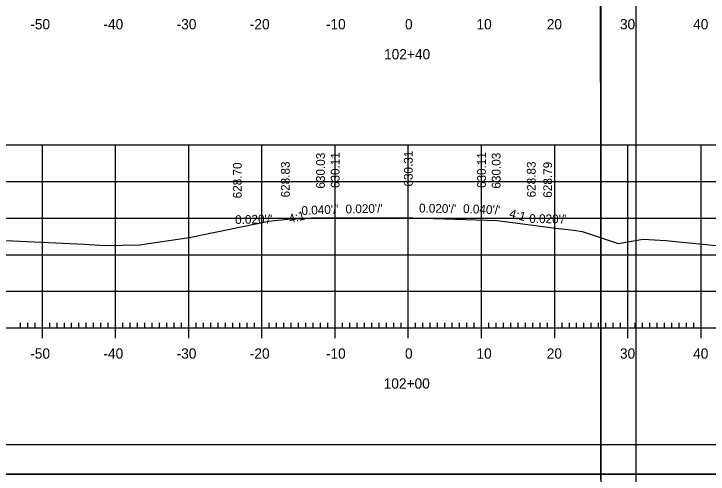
# Model space of a CAD drawing. Extents: x 1381471 to 1382703, y 370300 to 371487.
# Drawn here: x 1382082.7 to 1382177.6, y 370633.8 to 370696.7 of the extents above; entities that cross this region are included whole.
import ezdxf

# ---------------------------------------------------------------- set-up
doc = ezdxf.new("R2010")
doc.units = 0
for name, color, linetype in [('Level 26', 7, 'Continuous'), ('Level 45', 7, 'Continuous'), ('Level 6', 7, 'Continuous')]:
    doc.layers.add(name, color=color, linetype=linetype)

msp = doc.modelspace()

# ---------------------------------------------------------------- linework, layer by layer
at = {"layer": 'Level 26'}
for points in [[(1381834.365, 370760.966), (1382167.705, 370760.966), (1382167.705, 370547.628), (1381834.365, 370547.628)], [(1382080.692, 370757.071), (1382100.312, 370757.071), (1382100.312, 370747.191), (1382116.424, 370747.191), (1382139.624, 370747.191), (1382139.624, 370714.521), (1382162.831, 370714.521), (1382162.952, 370551.611), (1381846.772, 370551.611), (1381846.772, 370757.071)]]:
    msp.add_lwpolyline(points, close=True, dxfattribs=at)
at = {"layer": 'Level 45'}
for p, q in [((1381996.613, 370678.782), (1382276.613, 370678.782)), ((1382086.613, 370653.782), (1382086.613, 370678.782)), ((1382096.613, 370653.782), (1382096.613, 370678.782)), ((1382106.613, 370653.782), (1382106.613, 370678.782)), ((1382116.613, 370653.782), (1382116.613, 370678.782)), ((1382126.613, 370653.782), (1382126.613, 370678.782)), ((1382136.613, 370653.782), (1382136.613, 370678.782)), ((1382146.613, 370653.782), (1382146.613, 370678.782)), ((1382156.613, 370653.782), (1382156.613, 370678.782)), ((1382166.613, 370653.782), (1382166.613, 370678.782)), ((1382176.613, 370653.782), (1382176.613, 370678.782)), ((1381996.613, 370673.782), (1382276.613, 370673.782)), ((1381996.613, 370668.782), (1382276.613, 370668.782)), ((1381996.613, 370663.782), (1382276.613, 370663.782)), ((1381996.613, 370658.782), (1382276.613, 370658.782)), ((1382086.613, 370652.382), (1382086.613, 370655.182)), ((1382096.613, 370652.382), (1382096.613, 370655.182)), ((1382106.613, 370652.382), (1382106.613, 370655.182)), ((1382116.613, 370652.382), (1382116.613, 370655.182)), ((1382126.613, 370652.382), (1382126.613, 370655.182)), ((1382136.613, 370652.382), (1382136.613, 370655.182)), ((1382146.613, 370652.382), (1382146.613, 370655.182)), ((1382156.613, 370652.382), (1382156.613, 370655.182)), ((1382166.613, 370652.382), (1382166.613, 370655.182)), ((1382176.613, 370652.382), (1382176.613, 370655.182)), ((1381996.613, 370653.782), (1382276.613, 370653.782)), ((1381996.613, 370653.782), (1382276.613, 370653.782)), ((1382083.613, 370653.782), (1382083.613, 370654.482)), ((1382084.613, 370653.782), (1382084.613, 370654.482)), ((1382085.613, 370653.782), (1382085.613, 370654.482)), ((1382087.613, 370653.782), (1382087.613, 370654.482)), ((1382088.613, 370653.782), (1382088.613, 370654.482)), ((1382089.613, 370653.782), (1382089.613, 370654.482)), ((1382090.613, 370653.782), (1382090.613, 370654.482)), ((1382091.613, 370653.782), (1382091.613, 370654.482)), ((1382092.613, 370653.782), (1382092.613, 370654.482)), ((1382093.613, 370653.782), (1382093.613, 370654.482)), ((1382094.613, 370653.782), (1382094.613, 370654.482)), ((1382095.613, 370653.782), (1382095.613, 370654.482)), ((1382097.613, 370653.782), (1382097.613, 370654.482)), ((1382098.613, 370653.782), (1382098.613, 370654.482)), ((1382099.613, 370653.782), (1382099.613, 370654.482)), ((1382100.613, 370653.782), (1382100.613, 370654.482)), ((1382101.613, 370653.782), (1382101.613, 370654.482)), ((1382102.613, 370653.782), (1382102.613, 370654.482)), ((1382103.613, 370653.782), (1382103.613, 370654.482)), ((1382104.613, 370653.782), (1382104.613, 370654.482)), ((1382105.613, 370653.782), (1382105.613, 370654.482)), ((1382107.613, 370653.782), (1382107.613, 370654.482)), ((1382108.613, 370653.782), (1382108.613, 370654.482)), ((1382109.613, 370653.782), (1382109.613, 370654.482)), ((1382110.613, 370653.782), (1382110.613, 370654.482)), ((1382111.613, 370653.782), (1382111.613, 370654.482)), ((1382112.613, 370653.782), (1382112.613, 370654.482)), ((1382113.613, 370653.782), (1382113.613, 370654.482)), ((1382114.613, 370653.782), (1382114.613, 370654.482)), ((1382115.613, 370653.782), (1382115.613, 370654.482)), ((1382117.613, 370653.782), (1382117.613, 370654.482)), ((1382118.613, 370653.782), (1382118.613, 370654.482)), ((1382119.613, 370653.782), (1382119.613, 370654.482)), ((1382120.613, 370653.782), (1382120.613, 370654.482)), ((1382121.613, 370653.782), (1382121.613, 370654.482)), ((1382122.613, 370653.782), (1382122.613, 370654.482)), ((1382123.613, 370653.782), (1382123.613, 370654.482)), ((1382124.613, 370653.782), (1382124.613, 370654.482)), ((1382125.613, 370653.782), (1382125.613, 370654.482)), ((1382127.613, 370653.782), (1382127.613, 370654.482)), ((1382128.613, 370653.782), (1382128.613, 370654.482)), ((1382129.613, 370653.782), (1382129.613, 370654.482)), ((1382130.613, 370653.782), (1382130.613, 370654.482)), ((1382131.613, 370653.782), (1382131.613, 370654.482)), ((1382132.613, 370653.782), (1382132.613, 370654.482)), ((1382133.613, 370653.782), (1382133.613, 370654.482)), ((1382134.613, 370653.782), (1382134.613, 370654.482)), ((1382135.613, 370653.782), (1382135.613, 370654.482)), ((1382137.613, 370653.782), (1382137.613, 370654.482)), ((1382138.613, 370653.782), (1382138.613, 370654.482)), ((1382139.613, 370653.782), (1382139.613, 370654.482)), ((1382140.613, 370653.782), (1382140.613, 370654.482)), ((1382141.613, 370653.782), (1382141.613, 370654.482)), ((1382142.613, 370653.782), (1382142.613, 370654.482)), ((1382143.613, 370653.782), (1382143.613, 370654.482)), ((1382144.613, 370653.782), (1382144.613, 370654.482)), ((1382145.613, 370653.782), (1382145.613, 370654.482)), ((1382147.613, 370653.782), (1382147.613, 370654.482)), ((1382148.613, 370653.782), (1382148.613, 370654.482)), ((1382149.613, 370653.782), (1382149.613, 370654.482)), ((1382150.613, 370653.782), (1382150.613, 370654.482)), ((1382151.613, 370653.782), (1382151.613, 370654.482)), ((1382152.613, 370653.782), (1382152.613, 370654.482)), ((1382153.613, 370653.782), (1382153.613, 370654.482)), ((1382154.613, 370653.782), (1382154.613, 370654.482)), ((1382155.613, 370653.782), (1382155.613, 370654.482)), ((1382157.613, 370653.782), (1382157.613, 370654.482)), ((1382158.613, 370653.782), (1382158.613, 370654.482)), ((1382159.613, 370653.782), (1382159.613, 370654.482)), ((1382160.613, 370653.782), (1382160.613, 370654.482)), ((1382161.613, 370653.782), (1382161.613, 370654.482)), ((1382162.613, 370653.782), (1382162.613, 370654.482)), ((1382163.613, 370653.782), (1382163.613, 370654.482)), ((1382164.613, 370653.782), (1382164.613, 370654.482)), ((1382165.613, 370653.782), (1382165.613, 370654.482)), ((1382167.613, 370653.782), (1382167.613, 370654.482)), ((1382168.613, 370653.782), (1382168.613, 370654.482)), ((1382169.613, 370653.782), (1382169.613, 370654.482)), ((1382170.613, 370653.782), (1382170.613, 370654.482)), ((1382171.613, 370653.782), (1382171.613, 370654.482)), ((1382172.613, 370653.782), (1382172.613, 370654.482)), ((1382173.613, 370653.782), (1382173.613, 370654.482)), ((1382174.613, 370653.782), (1382174.613, 370654.482)), ((1382175.613, 370653.782), (1382175.613, 370654.482)), ((1382294.793, 370637.782), (1381978.613, 370637.782)), ((1381966.213, 370633.804), (1382299.546, 370633.804))]:
    msp.add_line(p, q, dxfattribs=at)
for points in [[(1381966.206, 370847.137), (1382299.546, 370847.137), (1382299.546, 370633.799), (1381966.206, 370633.799)], [(1382212.533, 370843.242), (1382232.153, 370843.242), (1382232.153, 370833.362), (1382248.266, 370833.362), (1382271.465, 370833.362), (1382271.465, 370809.03), (1382294.793, 370809.03), (1382294.793, 370637.782), (1381978.613, 370637.782), (1381978.613, 370843.242)]]:
    msp.add_lwpolyline(points, close=True, dxfattribs=at)
msp.add_lwpolyline([(1382063.87, 370666.561), (1382092.386, 370665.237), (1382095.135, 370665.057), (1382099.882, 370665.147), (1382106.653, 370666.12), (1382117.554, 370668.37), (1382119.293, 370668.543), (1382120.126, 370668.631), (1382122.264, 370668.745), (1382123.377, 370668.803), (1382124.276, 370668.806), (1382126.097, 370668.809), (1382137.234, 370668.841), (1382144.439, 370668.582), (1382148.754, 370668.443), (1382156.769, 370667.426), (1382159.211, 370667.12), (1382160.355, 370666.967), (1382160.915, 370666.753), (1382165.287, 370665.329), (1382168.706, 370665.887), (1382171.79, 370665.742), (1382185.03, 370664.383)], dxfattribs=at)
at = {"layer": 'Level 6'}
msp.add_line((1382162.952, 370551.611), (1382162.952, 370757.071), dxfattribs=at)

# ---------------------------------------------------------------- texts
at = {"layer": 'Level 45'}
for s, p in [('-50', (1382084.954, 370694.582)), ('-40', (1382094.954, 370694.582)), ('-30', (1382104.954, 370694.582)), ('-20', (1382114.954, 370694.582)), ('-10', (1382125.351, 370694.582)), ('0', (1382136.156, 370694.582)), ('10', (1382145.924, 370694.582)), ('20', (1382155.528, 370694.582)), ('30', (1382165.528, 370694.582)), ('40', (1382175.528, 370694.582)), ('102+40', (1382133.301, 370690.482)), ('-50', (1382084.954, 370649.582)), ('-40', (1382094.954, 370649.582)), ('-30', (1382104.954, 370649.582)), ('-20', (1382114.954, 370649.582)), ('-10', (1382125.351, 370649.582)), ('0', (1382136.156, 370649.582)), ('10', (1382145.924, 370649.582)), ('20', (1382155.528, 370649.582)), ('30', (1382165.528, 370649.582)), ('40', (1382175.528, 370649.582)), ('102+00', (1382133.246, 370645.482))]:
    msp.add_text(s, height=1.4, dxfattribs=at).set_placement(p)
for s, rotation, p in [('630.03', 90, (1382125.213, 370672.812)), ('630.11', 90, (1382127.213, 370672.892)), ('630.31', 90, (1382137.213, 370673.092)), ('630.11', 90, (1382147.213, 370672.892)), ('630.03', 90, (1382149.213, 370672.812)), ('628.83', 90, (1382120.413, 370671.612)), ('628.83', 90, (1382154.013, 370671.612)), ('628.70', 90, (1382113.847, 370671.481)), ('628.79', 90, (1382156.253, 370671.567)), ("0.020'/'", 1.14576, (1382128.042, 370669.421)), ("0.020'/'", 358.85424, (1382138.062, 370669.563)), ("0.040'/'", 2.29061, (1382122.034, 370669.21)), ("0.040'/'", 357.70939, (1382144.074, 370669.494)), ('4:1', 345.96376, (1382150.328, 370668.899)), ("0.020'/'", 1.14576, (1382112.959, 370667.975)), ('4:1', 14.03624, (1382120.427, 370668.081)), ("0.020'/'", 358.85424, (1382153.123, 370668.144))]:
    msp.add_text(s, height=1.2, rotation=rotation, dxfattribs=at).set_placement(p)

doc.saveas('drawing.dxf')
